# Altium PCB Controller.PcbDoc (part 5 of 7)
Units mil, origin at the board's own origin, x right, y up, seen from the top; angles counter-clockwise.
Board outline 9000 x 8000 mil, 6 copper layers (Top Layer, Layer 1, Layer 2, Layer 3, Layer 4, Bottom Layer), stack 61.699 mil thick; 761 components, 454 nets, 2369 pads, 1133 vias.
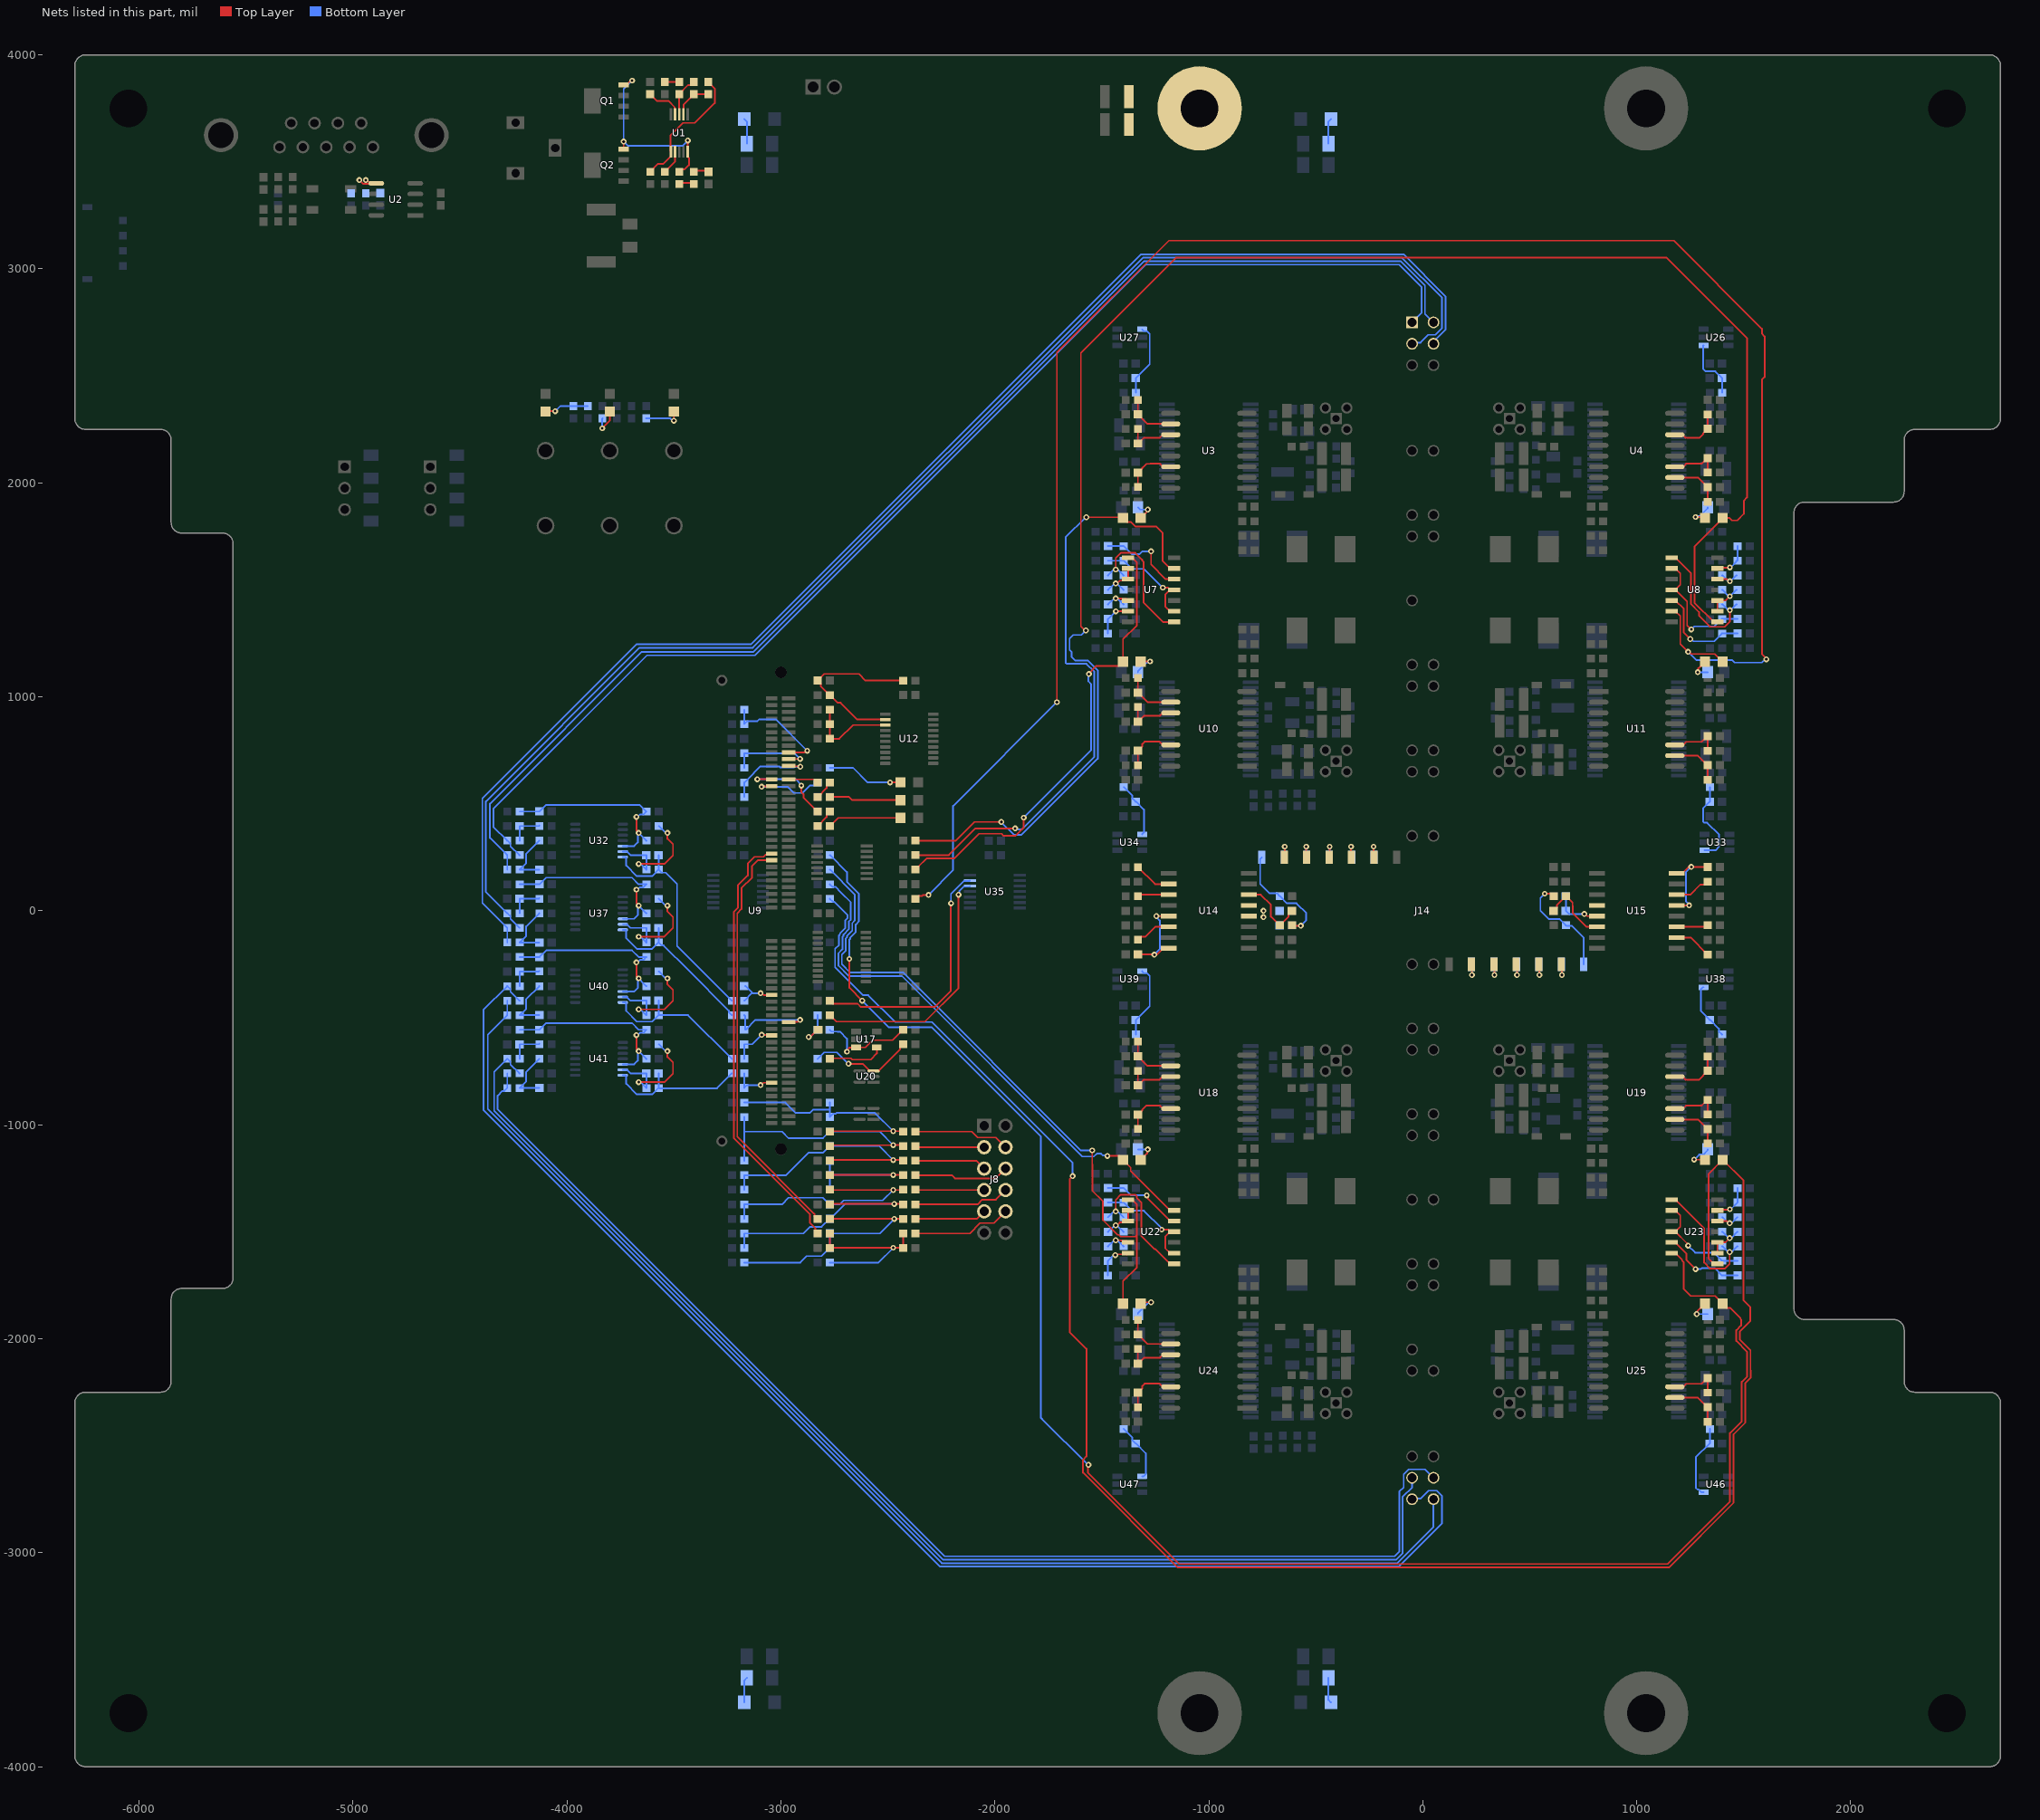
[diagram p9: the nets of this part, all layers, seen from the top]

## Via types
v1: diameter 27, hole 13, Top Layer to Bottom Layer, tented both sides, 1133 vias

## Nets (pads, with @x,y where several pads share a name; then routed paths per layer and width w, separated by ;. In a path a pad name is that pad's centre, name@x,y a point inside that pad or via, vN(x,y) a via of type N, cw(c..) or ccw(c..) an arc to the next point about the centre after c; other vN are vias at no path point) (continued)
GPIO22: R133.2 U9.72 | length 1938
  Top Layer w8: U9.72@-3042.32,236.22 -3108.78,236.22 -3135,210 -3135,155 -3184,106 -3184,8.37 -3204,-11.63 -3204,-1056 -2843.2,-1416.8 -2843.2,-1426.04 -2829.25,-1440 R133.2@-2828.62,-1440
GPIO23: R135.2 U9.74 | length 2049.9
  Top Layer w8: U9.74@-3042.32,267.72 -3048.17,261.87 -3071.48,261.87 -3081.13,252.22 -3123.56,252.22 -3155,220.78 -3155,165 -3200,120 -3200,15 -3220,-5 -3220,-1062.63 -2865,-1417.63 -2865,-1457.41 -2839.68,-1482.73 -2839.68,-1496.94 R135.2@-2828.62,-1508
HLDOO_N: C172.1 C174.1 U15.5 | length 223.3
  Top Layer w8: v1(755,-15) 758.46,-15 768.46,-25 U15.5@813.5,-25
  Bottom Layer w8: C172.1@668.58,68 C174.1@668.58,0 683.44,-14.86 715.24,-14.86 715.38,-15 v1(755,-15)
HLDOO_P: C175.1 C177.1 U14.5
  other v1: -745,-30 -745,0
IAC+_P: J14.004 R268.1 R271.1 | length 6602.4
  Bottom Layer w8: R271.1@-4278.62,-148 R268.1@-4278.62,-80 -4279.53,-80 -4395,35.47 -4395,525 -3675,1245 -3140,1245 -1317,3068 -90.12,3068 106,2871.88 106,2716 50,2660 J14.004@50,2650
IAC+_S: J14.110 R305.1 R310.1 | length 5815.8
  Bottom Layer w8: R305.1@-4278.62,-760 R310.1@-4278.62,-828 -4292.58,-841.96 -4301.96,-841.96 -4324,-864 -4324,-928.12 -2235.12,-3017 -132,-3017 -110,-2995 -110,-2715 -89.36,-2694.36 -89.36,-2633.7 -66.3,-2610.64 10.64,-2610.64 J14.110@50,-2650
IAC-_P: J14.003 R266.1 R268.2 | length 6569.5
  Bottom Layer w8: R268.2@-4221.38,-80 -4222.28,-80 -4263.76,-38.52 -4263.76,-25.96 -4277.72,-12 R266.1@-4278.62,-12 -4279.53,-12 -4379,87.47 -4379,511 -3661,1229 -3131.25,1229 -1308.25,3052 -96.75,3052 90,2865.25 90,2722.63 59.08,2691.71 25.86,2691.71 -10.64,2655.21 -44.79,2655.21 J14.003@-50,2650
IAC-_S: J14.109 R302.1 R305.2 | length 5859.4
  Bottom Layer w8: R305.2@-4221.38,-760 -4222.28,-760 -4263.76,-718.52 -4263.76,-705.96 -4277.72,-692 R302.1@-4278.62,-692 -4279.53,-692 -4340,-752.47 -4340,-934.75 -2241.75,-3033 -125.37,-3033 -94,-3001.63 -94,-2738.33 -50,-2694.33 J14.109@-50,-2650
IAC_P: C199.1 R285.2 U9.31 | length 403.7
  Top Layer w8: U9.31@-2963.58,-519.69 -2923.46,-519.69 -2913.78,-510 v1(-2910,-510)
  Bottom Layer w8: R285.2@-3171.38,-488 -3167.45,-491.93 -3167.45,-556 -3164.57,-556 -3118.57,-510 v1(-2910,-510)
IAC_S: C214.1 R304.2 U9.14 | length 207.3
  Top Layer w8: v1(-3095,-815) -3092.24,-815 -3080.9,-803.66 -3042.83,-803.66 U9.14@-3042.32,-803.15
  Bottom Layer w8: C214.1@-3171.42,-828 C214.1@-3171.42,-828 ; R304.2@-3171.38,-760 C214.1@-3171.42,-828 ; v1(-3095,-815) -3158.42,-815 C214.1@-3171.42,-828
ID0: R234.1 R241.2 U9.99 | length 420.8
  Top Layer w8: U9.99@-2963.58,677.17 -2961.68,675.26 -2911.4,675.26 v1(-2909.49,673.35)
  Bottom Layer w8: R241.2@-3171.38,532 R234.1@-3171.38,600 -3170.47,600 -3126.29,644.18 -3126.29,644.77 -3096.06,675 -3007.96,675 -3002.5,669.55 -2938.99,669.55 -2935.19,673.35 v1(-2909.49,673.35)
ID1: R227.2 R230.1 U9.101 | length 393.2
  Top Layer w8: U9.101@-2963.58,708.66 -2963.18,709.07 -2910.93,709.07 v1(-2910.53,709.47)
  Bottom Layer w8: R230.1@-3171.38,668 R227.2@-3171.38,736 -2937.06,736 v1(-2910.53,709.47)
ID2: R218.1 R222.2 U9.103 | length 525.5
  Top Layer w8: U9.103@-2963.5,740.08 U9.103@-2963.58,740.16 -2889.98,740.16 -2880,750.14 v1@-2880,755
  Bottom Layer w8: R218.1@-3171.38,940 R222.2@-3171.38,872 -3157.42,885.96 -3110.11,885.96 -3101.06,895 -3023.94,895 v1(-2876.97,748.03)
IDC+_P: J14.002 R250.1 R256.1 | length 5998.8
  Bottom Layer w8: R256.1@-4278.62,192 R250.1@-4278.62,260 -4279.53,260 -4360,340.47 -4360,500 -3650,1210 -3127.63,1210 -1301.63,3036 -181,3036 -103.37,3036 10,2922.63 10,2845 10,2790 J14.002@50,2750
IDC+_S: J14.112 R283.1 R287.1 | length 6044.7
  Bottom Layer w8: R283.1@-4278.62,-420 R287.1@-4278.62,-488 -4279.53,-488 -4370,-578.47 -4370,-927.37 -2248.37,-3049 -118.75,-3049 50,-2880.26 J14.112@50,-2750
IDC-_P: J14.001 R248.1 R250.2 | length 5887.4
  Bottom Layer w8: R250.2@-4221.38,260 -4222.28,260 -4263.76,301.48 -4263.76,314.04 -4277.72,328 R248.1@-4278.62,328 -4279.53,328 -4344,392.47 -4344,476 -3626,1194 -3121,1194 -1295,3020 -110,3020 -6,2916 -6,2794 J14.001@-50,2750
IDC-_S: J14.111 R281.1 R283.2 | length 6460.2
  Bottom Layer w8: R283.2@-4221.38,-420 -4222.28,-420 -4263.76,-378.52 -4263.76,-365.96 -4277.72,-352 R281.1@-4278.62,-352 -4279.53,-352 -4390,-462.47 -4390,-930 -2255,-3065 -112.12,-3065 89.36,-2863.52 89.36,-2733.7 65.67,-2710 27.14,-2710 -10.64,-2747.77 -47.77,-2747.77 J14.111@-50,-2750
IDC_P: C190.1 R282.2 U9.40 | length 196.7
  Top Layer w8: v1(-3095,-385) -3089.86,-385 -3081.16,-393.7 U9.40@-3042.32,-393.7
  Bottom Layer w8: R282.2@-3171.38,-420 -3170.47,-420 -3135.47,-385 -3131.57,-385 ; C190.1@-3167.45,-352 -3164.57,-352 -3131.57,-385 ; v1(-3095,-385) -3131.57,-385
IDC_S: C202.1 R299.2 U9.28 | length 220
  Top Layer w8: v1(-3089.7,-579.7) -3088.22,-581.19 -3043.81,-581.19 U9.28@-3042.32,-582.68
  Bottom Layer w8: R299.2@-3171.38,-692 C202.1@-3171.42,-624 C202.1@-3171.42,-624 -3134,-624 v1(-3089.7,-579.7) v1@-3087.35,-577.35
INP_P: C46.1 R76.2 U14.6 | length 329.1
  Top Layer w8: U14.6@-813.5,75 -757.63,75 -710,27.37 -710,-27.53 -669.53,-68 R76.2@-668.62,-68 -667.72,-68 -627.24,-27.52 -627.24,-14.86 -612.37,0 C46.1@-611.42,0
INP_S: C47.1 R72.2 U15.6 | length 324.7
  Top Layer w8: C47.1@611.42,0 612.37,0 627.24,14.86 627.24,27.52 667.72,68 R72.2@668.62,68 669.53,68 700,37.53 700,24.22 700.39,23.83 700.39,-10.39 765,-75 U15.6@813.5,-75
LED_G: R60.2 U9.96 | length 441.9
  Top Layer w8: v1(-3110.33,614.67) -3110.09,614.42 -3042.57,614.42 U9.96@-3042.32,614.17 ; v1(-2904.6,585) -2904.6,554.6 -2894.48,544.48 -2894.48,528.96 -2829.53,464 R60.2@-2828.62,464
  Bottom Layer w8: v1(-3110.33,614.67) -2929.67,614.67 -2904.6,589.6 v1(-2904.6,585)
LED_R: R233.2 U9.94 | length 343.6
  Top Layer w8: v1(-3090.33,579.67) -3088.83,581.17 -3043.83,581.17 U9.94@-3042.32,582.68
  Bottom Layer w8: v1(-3090.33,579.67) -2968.8,579.67 -2939.57,550.43 -2898.5,550.43 -2862.89,586.04 -2842.58,586.04 R233.2@-2828.62,600
LED_Y: R58.2 U9.95 | length 139.9
  Top Layer w8: U9.95@-2963.58,614.17 -2843.7,614.17 R58.2@-2829.53,600
NCP_NOTUSED: U14.4
NCS_NOTUSED: U15.4
NetC1_1: C1.1 U1.4 | length 174.2
  Top Layer w8: C1.1@-3611,3816.42 -3611,3815.47 -3580.53,3785 -3526.36,3785 -3496.47,3755.11 -3496.47,3723.87 U1.4@-3494.68,3722.09
NetC2_1: C2.1 R10.1 | length 70
  Top Layer w8: R10.1@-3400,3458.62 -3330.04,3458.62 C2.1@-3330,3458.58
NetC10_1: C10.1 R16.2 U3.10 | length 240.3
  Top Layer w8: R16.2@-1331.38,2388 C10.1@-1331.42,2320 C10.1@-1331.42,2320 -1330.47,2320 -1285.97,2275.5 -1178.28,2275.5 U3.10@-1177.78,2275
NetC13_1: C13.1 R17.2 U4.14 | length 227.8
  Top Layer w8: U4.14@1196.73,2225 1214.82,2225 1229.82,2210 1276.21,2210 1276.59,2210.38 1291.44,2210.38 1310.5,2229.44 1310.5,2232.03 1330.47,2252 C13.1@1331.42,2252 C13.1@1331.42,2252 R17.2@1331.38,2320
NetC14_1: C14.1 R18.2 U3.11 | length 238.6
  Top Layer w8: R18.2@-1331.38,2252 C14.1@-1331.42,2184 C14.1@-1331.42,2184 -1330.47,2184 -1303.97,2210.5 -1230.18,2210.5 -1215.68,2225 U3.11@-1177.78,2225
NetC15_1: C15.1 R23.2 U4.11 | length 238.6
  Top Layer w8: U4.11@1177.78,2075 1215.68,2075 1230.18,2089.5 1303.97,2089.5 1330.47,2116 C15.1@1331.42,2116 C15.1@1331.42,2116 R23.2@1331.38,2048
NetC16_1: C16.1 R26.2 U3.14 | length 227.8
  Top Layer w8: R26.2@-1331.38,1980 C16.1@-1331.42,2048 C16.1@-1331.42,2048 -1330.47,2048 -1310.5,2067.97 -1310.5,2070.56 -1292.09,2088.97 -1273.91,2088.97 -1272.88,2090 -1229.82,2090 -1214.82,2075 U3.14@-1196.73,2075
NetC17_1: C17.1 R27.2 U4.10 | length 240.3
  Top Layer w8: U4.10@1177.78,2025 1178.28,2024.5 1285.97,2024.5 1330.47,1980 C17.1@1331.42,1980 C17.1@1331.42,1980 R27.2@1331.38,1912
NetC24_1: C24.1 R41.1 R45.2 U12.2 | length 823.9
  Top Layer w8: C24.1@-2828.58,1076 C24.1@-2827.63,1076 ; U12.2@-2512.2,893.57 -2642.5,893.57 -2721.24,972.3 -2734.78,972.3 -2770.47,1008 R45.2@-2771.38,1008 -2772.28,1008 -2812.76,1048.48 -2812.76,1061.14 C24.1@-2827.63,1076 ; R41.1@-2428.62,1076 -2604.41,1076 -2635.28,1106.86 -2796.76,1106.86 C24.1@-2827.63,1076
NetC25_1: C25.1 R40.2 U10.10 | length 240.3
  Top Layer w8: R40.2@-1331.38,1088 C25.1@-1331.42,1020 C25.1@-1331.42,1020 -1330.47,1020 -1285.97,975.5 -1178.28,975.5 U10.10@-1177.78,975
NetC28_1: C28.1 R46.2 U10.11 | length 238.6
  Top Layer w8: R46.2@-1331.38,952 C28.1@-1331.42,884 C28.1@-1331.42,884 -1330.47,884 -1303.97,910.5 -1230.18,910.5 -1215.68,925 U10.11@-1177.78,925
NetC29_1: C29.1 R47.1 R52.2 U12.3 | length 421.7
  Top Layer w8: R47.1@-2771.38,940 R47.1@-2771.38,940 C29.1@-2771.42,872 C29.1@-2771.42,872 R52.2@-2771.38,804 -2727.22,804 -2663.25,867.98 U12.3@-2512.2,867.98
NetC30_1: C30.1 R53.2 U11.11 | length 238.6
  Top Layer w8: U11.11@1177.78,775 1215.68,775 1230.18,789.5 1303.97,789.5 1330.47,816 C30.1@1331.42,816 C30.1@1331.42,816 R53.2@1331.38,748
NetC31_1: C31.1 R55.2 U10.14 | length 232.1
  Top Layer w8: R55.2@-1331.38,680 C31.1@-1331.42,748 C31.1@-1331.42,748 ; C31.1@-1330.47,748 -1310.5,767.97 -1310.5,779.5 -1300,790 -1229.82,790 -1214.82,775 U10.14@-1196.73,775
NetC34_1: C34.1 R57.2 U11.10 | length 240.3
  Top Layer w8: U11.10@1177.78,725 1178.28,724.5 1285.97,724.5 1330.47,680 C34.1@1331.42,680 C34.1@1331.42,680 R57.2@1331.38,612
NetC39_1: C39.1 U15.13 U15.16 | length 412.4
  Top Layer w8: U15.13@1186.5,25 v1(1245,25) ; U15.16@1186.5,175 1212.5,175 1241.5,204 C39.1@1331.42,204
  Bottom Layer w8: v1(1245,25) 1245,30.06 1229.5,45.56 1229.5,179.5 v1(1255,205)
NetC52_1: C52.1 U14.13 U14.16 | length 412.4
  Top Layer w8: C52.1@-1331.42,-204 -1241.5,-204 -1212.5,-175 U14.16@-1186.5,-175 ; v1(-1245,-25) U14.13@-1186.5,-25
  Bottom Layer w8: v1(-1255,-205) -1229.5,-179.5 -1229.5,-45.56 -1245,-30.06 v1(-1245,-25)
NetC54_1: C54.1 R288.2 U17.3 | length 467.7
  Top Layer w8: v1(-2691.44,-658.56) -2687.8,-654.93 -2687.8,-647.8 -2680.17,-640.17 -2650,-640.17 U17.3@-2648.23,-638.4 -2605.16,-638.4 -2571.39,-604.63 -2478.16,-604.63 -2429.53,-556 C54.1@-2428.58,-556
  Bottom Layer w8: R288.2@-2771.38,-556 -2762.88,-564.5 -2735.5,-564.5 -2735.19,-564.81 -2724.12,-564.81 -2691.44,-597.5 v1(-2691.44,-658.56)
NetC59_1: C59.1 R94.2 U18.10 | length 240.3
  Top Layer w8: R94.2@-1331.38,-612 C59.1@-1331.42,-680 C59.1@-1331.42,-680 -1330.47,-680 -1285.97,-724.5 -1178.28,-724.5 U18.10@-1177.78,-725
NetC62_1: C62.1 R96.2 U19.14 | length 227.8
  Top Layer w8: U19.14@1196.73,-775 1214.82,-775 1229.82,-790 1276.21,-790 1276.59,-789.62 1291.44,-789.62 1310.5,-770.56 1310.5,-767.97 1330.47,-748 C62.1@1331.42,-748 C62.1@1331.42,-748 R96.2@1331.38,-680
NetC63_1: C63.1 R99.2 U18.11 | length 238.6
  Top Layer w8: R99.2@-1331.38,-748 C63.1@-1331.42,-816 C63.1@-1331.42,-816 -1330.47,-816 -1303.97,-789.5 -1230.18,-789.5 -1215.68,-775 U18.11@-1177.78,-775
NetC65_1: C65.1 R109.2 U19.11 | length 238.6
  Top Layer w8: U19.11@1177.78,-925 1215.68,-925 1230.18,-910.5 1303.97,-910.5 1330.47,-884 C65.1@1331.42,-884 C65.1@1331.42,-884 R109.2@1331.38,-952
NetC66_1: C66.1 R113.2 U18.14 | length 227.8
  Top Layer w8: R113.2@-1331.38,-1020 C66.1@-1331.42,-952 C66.1@-1331.42,-952 -1330.47,-952 -1310.5,-932.03 -1310.5,-929.44 -1291.44,-910.38 -1276.59,-910.38 -1276.21,-910 -1229.82,-910 -1214.82,-925 U18.14@-1196.73,-925
NetC68_1: C68.1 R116.2 U19.10 | length 240.3
  Top Layer w8: U19.10@1177.78,-975 1178.28,-975.5 1285.97,-975.5 1330.47,-1020 C68.1@1331.42,-1020 C68.1@1331.42,-1020 R116.2@1331.38,-1088
NetC72_1: C72.1 R135.1 R136.2 R137.1 R351.2 | length 804.6
  Top Layer w8: R135.1@-2771.38,-1508 R137.1@-2771.38,-1576 -2770.38,-1575 v1(-2475,-1575) -2429.58,-1575 C72.1@-2428.58,-1576 R136.2@-2428.62,-1508 R136.2@-2428.62,-1508
  Bottom Layer w8: R351.2@-2771.38,-1644 -2544,-1644 v1(-2475,-1575)
NetC76_1: C76.1 R144.2 U24.10 | length 240.3
  Top Layer w8: R144.2@-1331.38,-1912 C76.1@-1331.42,-1980 C76.1@-1331.42,-1980 -1330.47,-1980 -1285.97,-2024.5 -1178.28,-2024.5 U24.10@-1177.78,-2025
NetC78_1: C78.1 R148.2 U24.11 | length 238.6
  Top Layer w8: R148.2@-1331.38,-2048 C78.1@-1331.42,-2116 C78.1@-1331.42,-2116 -1330.47,-2116 -1303.97,-2089.5 -1230.18,-2089.5 -1215.68,-2075 U24.11@-1177.78,-2075
NetC79_1: C79.1 R153.2 U25.11 | length 238.6
  Top Layer w8: U25.11@1177.78,-2225 1215.68,-2225 1230.18,-2210.5 1303.97,-2210.5 1330.47,-2184 C79.1@1331.42,-2184 C79.1@1331.42,-2184 R153.2@1331.38,-2252
NetC80_1: C80.1 R154.2 U24.14 | length 232.1
  Top Layer w8: R154.2@-1331.38,-2320 C80.1@-1331.42,-2252 C80.1@-1331.42,-2252 ; C80.1@-1330.47,-2252 -1310.5,-2232.03 -1310.5,-2220.5 -1300,-2210 -1229.82,-2210 -1214.82,-2225 U24.14@-1196.73,-2225
NetC83_1: C83.1 R155.2 U25.10 | length 240.3
  Top Layer w8: U25.10@1177.78,-2275 1178.28,-2275.5 1285.97,-2275.5 1330.47,-2320 C83.1@1331.42,-2320 C83.1@1331.42,-2320 R155.2@1331.38,-2388
NetC87_1: C87.1 R160.1 R161.1 U2.5 | length 111.6
  Top Layer w8: v1(-4970,3415) -4952.45,3397.45 U2.5@-4920.82,3397.45 ; v1(-4940,3415) -4935.82,3415 -4920.82,3400 U2.5@-4891.09,3400
NetC91_1: C91.1 R162.1 U26.1 | length 284.7
  Bottom Layer w8: U26.1@1311.93,2642.6 1309.61,2640.28 1309.61,2534.17 1322.91,2520.86 1366.76,2520.86 1397.63,2490 C91.1@1398.58,2490 C91.1@1398.58,2490 R162.1@1398.62,2422
NetC92_1: C92.1 R163.1 U27.1 | length 346.4
  Bottom Layer w8: R163.1@-1341.38,2422 C92.1@-1341.42,2490 C92.1@-1341.42,2490 -1340.47,2490 -1276.31,2554.17 -1276.31,2696.64 -1288.27,2708.61 -1303.13,2708.61 U27.1@-1311.93,2717.4
NetC116_1: C116.1 R192.1 U7.5 | length 420.1
  Top Layer w8: v1(-1270,1680) -1270,1618.46 -1201.54,1550 U7.5@-1162.75,1550
  Bottom Layer w8: C116.1@-1471.42,1704 R192.1@-1398.62,1704 -1397.72,1704 -1359.67,1665.96 -1324.43,1665.96 -1310.38,1680 v1(-1270,1680)
NetC117_1: C117.1 R191.1 U8.13 | length 174.1
  Top Layer w8: U8.13@1377.25,1600 1379.75,1602.5 1432.5,1602.5 v1(1435,1605)
  Bottom Layer w8: v1(1435,1605) 1439.47,1605 1465.47,1631 C117.1@1465.47,1636 ; C117.1@1471.42,1636 R191.1@1471.38,1704 R191.1@1471.38,1704
NetC118_1: C118.1 R194.1 U7.2 U7.4 | length 501.8
  Top Layer w8: v1(-1215,1510) -1190.5,1510 U7.4@-1180.5,1500 ; U7.2@-1162.75,1400 -1180.5,1400 -1203.5,1423 -1203.5,1477 U7.4@-1180.5,1500 ; U7.4@-1162.75,1500 U7.4@-1180.5,1500
  Bottom Layer w8: C118.1@-1471.42,1636 R194.1@-1398.62,1636 -1397.72,1636 -1359.67,1597.96 -1302.96,1597.96 v1(-1215,1510)
NetC119_1: C119.1 R195.1 U8.12 | length 152.9
  Top Layer w8: U8.12@1377.25,1550 1419.86,1550 1429.86,1540 v1(1435,1540)
  Bottom Layer w8: R195.1@1398.62,1568 1399.53,1568 1423.89,1543.64 1431.36,1543.64 v1(1435,1540) 1437.47,1540 1465.47,1568 C119.1@1466.38,1568
NetC120_1: C120.1 R196.1 U7.1 | length 679.1
  Top Layer w8: v1(-1435,1595) -1435,1648.97 -1410.97,1673 -1343.53,1673 -1311.4,1640.87 -1311.4,1637.23 -1305.5,1631.34 -1305.5,1440.5 -1215,1350 U7.1@-1162.75,1350
  Bottom Layer w8: C120.1@-1471.42,1568 -1470.47,1568 -1447.11,1591.36 -1438.64,1591.36 v1(-1435,1595) -1431.36,1591.36 -1422.89,1591.36 -1399.53,1568 R196.1@-1398.62,1568
NetC121_1: C121.1 R197.1 U8.9 U8.10 | length 208.7
  Top Layer w8: U8.9@1377.25,1400 U8.10@1377.25,1450 1415,1450 v1(1435,1470)
  Bottom Layer w8: R197.1@1398.62,1500 1399.53,1500 1425.89,1473.64 1431.36,1473.64 v1(1435,1470) 1435.47,1470 1465.47,1500 C121.1@1466.38,1500
NetC122_1: C122.1 R198.1 U7.9 U7.10 | length 213.7
  Top Layer w8: v1(-1435,1530) -1429.86,1530 -1416.86,1543 -1384.25,1543 U7.10@-1377.25,1550 U7.9@-1377.25,1600
  Bottom Layer w8: C122.1@-1471.42,1500 -1470.47,1500 -1444.11,1526.36 -1438.64,1526.36 v1(-1435,1530) -1431.36,1526.36 -1425.89,1526.36 -1399.53,1500 R198.1@-1398.62,1500
NetC123_1: C123.1 R199.1 U8.1 | length 653.8
  Top Layer w8: U8.1@1162.75,1650 1180.5,1650 1254,1576.5 1254,1432.87 1291,1395.87 1291,1379.53 1343.53,1327 1410.97,1327 1435,1351.03 v1(1435,1405)
  Bottom Layer w8: R199.1@1398.62,1432 1399.53,1432 1422.89,1408.64 1431.36,1408.64 v1(1435,1405) 1438.47,1405 1465.47,1432 C123.1@1466.38,1432
NetC124_1: C124.1 R200.1 U7.12 | length 157.9
  Top Layer w8: v1(-1435,1460) -1409.5,1460 -1406.5,1457 -1384.25,1457 U7.12@-1377.25,1450
  Bottom Layer w8: C124.1@-1471.42,1432 -1470.47,1432 -1446.11,1456.36 -1438.64,1456.36 v1(-1435,1460) -1431.36,1456.36 -1423.89,1456.36 -1399.53,1432 R200.1@-1398.62,1432
NetC125_1: C125.1 R201.1 U8.2 U8.4 | length 606.5
  Top Layer w8: U8.4@1162.75,1500 U8.4@1180.5,1500 ; U8.2@1162.75,1600 1180.5,1600 1203.5,1577 1203.5,1523 U8.4@1180.5,1500 ; v1(1254.5,1315) 1235.5,1334 1235.5,1445 U8.4@1180.5,1500
  Bottom Layer w8: v1(1254.5,1315) 1268.78,1329.28 1363,1329.28 R201.1@1397.72,1364 ; R201.1@1398.62,1364 C125.1@1471.42,1364
NetC126_1: C126.1 R204.1 U7.13 | length 176.2
  Top Layer w8: v1(-1434.75,1399.8) -1434.65,1399.9 -1377.35,1399.9 U7.13@-1377.25,1400
  Bottom Layer w8: R204.1@-1471.38,1296 C126.1@-1471.42,1364 C126.1@-1471.42,1364 ; C126.1@-1470.47,1364 -1434.75,1399.73 v1(-1434.75,1399.8)
NetC127_1: C127.1 R203.1 U8.5 | length 467.4
  Top Layer w8: U8.5@1162.75,1450 1180.5,1450 1219.5,1411 1219.5,1300.5 v1(1250,1270)
  Bottom Layer w8: v1(1250,1270) 1255.14,1270 1265.64,1259.5 1361.22,1259.5 1397.72,1296 R203.1@1398.62,1296 C127.1@1471.42,1296
NetC152_1: C152.1 R235.1 U33.1 | length 406.3
  Bottom Layer w8: U33.1@1316.93,282.6 1367.6,282.6 1385,300 1385,355 1328.86,411.14 1316.64,411.14 1309.61,418.17 1309.61,479.14 1340.47,510 C152.1@1341.42,510 R235.1@1341.38,578 R235.1@1341.38,578 R235.1@1342.28,578
NetC153_1: C153.1 R236.1 U34.1 | length 265.3
  Bottom Layer w8: R236.1@-1398.62,578 -1397.72,578 -1357.24,537.52 -1357.24,524.86 -1342.37,510 C153.1@-1341.42,510 -1340.47,510 -1303.32,472.85 -1303.32,366.01 U34.1@-1311.93,357.4
NetC156_1: C156.1 R242.1 R243.2 R246.2 U32.12 | length 929.4
  Top Layer w8: v1(-3675,439) -3675,374 v1(-3665,364)
  Bottom Layer w8: R243.2@-4221.38,464 C156.1@-4128.58,464 -4127.63,464 -4096.76,494.86 -3660.39,494.86 -3629.53,464 R242.1@-3628.62,464 -3642.58,450.04 -3658.81,450.04 -3669.86,439 v1(-3675,439) ; U32.12@-3738.78,302.41 -3685.53,302.41 -3668.44,319.5 -3668.44,360.56 v1(-3665,364) -3664.62,364 -3652.44,351.81 -3652.44,350.91 -3629.53,328 R246.2@-3628.62,328
NetC161_1: C161.1 R245.1 R248.2 | length 162.1
  Bottom Layer w8: R248.2@-4221.38,328 C161.1@-4221.42,396 C161.1@-4221.42,396 -4131.62,396 R245.1@-4128.62,399
NetC167_1: C167.1 R244.2 R255.2 U32.13 | length 566.1
  Top Layer w8: v1(-3665,219) -3545,219 -3504.5,259.5 -3504.5,310.9 -3530,336.4 v1(-3530,364)
  Bottom Layer w8: U32.13@-3738.78,276.82 -3719.94,276.82 -3703.12,260 C167.1@-3628.58,260 C167.1@-3628.58,260 R255.2@-3628.62,192 -3629.53,192 v1@-3652.89,215.36 ; R244.2@-3571.38,396 -3570.47,396 -3542.11,367.64 -3533.64,367.64 v1(-3530,364)
NetC167_2: C167.2 R255.1 R282.1 U32.14 | length 1072.2
  Bottom Layer w8: U32.14@-3738.78,251.23 -3725.42,251.23 -3722.75,248.56 -3722.75,211.75 -3673.04,162.04 -3602.24,162.04 -3572.28,192 R255.1@-3571.38,192 ; C167.2@-3571.42,260 R255.1@-3571.38,192 R255.1@-3571.38,192 ; R282.1@-3228.62,-420 -3229.53,-420 -3485.43,-164.1 -3485.43,125.43 -3538.04,178.04 -3557.42,178.04 R255.1@-3571.38,192
NetC169_1: C169.1 R247.1 R256.2 | length 287.1
  Bottom Layer w8: R256.2@-4207.42,205.96 R256.2@-4221.38,192 R256.2@-4220.47,192 ; C169.1@-4128.58,192 R256.2@-4220.47,192 ; R247.1@-4128.62,328 -4129.53,328 -4190.5,267.03 -4190.5,221.97 R256.2@-4220.47,192
NetC171_1: C171.1 R258.1 R259.2 R264.2 U37.12 | length 929.4
  Top Layer w8: v1(-3675,99) -3675,34 v1(-3665,24)
  Bottom Layer w8: R259.2@-4221.38,124 C171.1@-4128.58,124 -4127.63,124 -4096.76,154.86 -3695.86,154.86 -3665,124 R258.1@-3628.62,124 -3642.58,110.04 -3658.81,110.04 -3669.86,99 v1(-3675,99) ; U37.12@-3738.78,-37.59 -3685.53,-37.59 -3668.44,-20.5 -3668.44,20.56 v1(-3665,24) -3664.62,24 -3652.44,11.81 -3652.44,10.91 -3629.53,-12 R264.2@-3628.62,-12
NetC173_1: C173.1 R263.1 R266.2 | length 162.1
  Bottom Layer w8: R266.2@-4221.38,-12 C173.1@-4221.42,56 C173.1@-4221.42,56 -4131.62,56 R263.1@-4128.62,59
NetC180_1: C180.1 R262.2 R270.2 U37.13 | length 566.1
  Top Layer w8: v1(-3665,-121) -3545,-121 -3504.5,-80.5 -3504.5,-29.1 -3530,-3.6 v1(-3530,24)
  Bottom Layer w8: U37.13@-3738.78,-63.18 -3719.94,-63.18 -3703.12,-80 C180.1@-3628.58,-80 C180.1@-3628.58,-80 R270.2@-3628.62,-148 -3629.53,-148 v1@-3652.89,-124.64 ; R262.2@-3571.38,56 -3570.47,56 -3542.11,27.64 -3533.64,27.64 v1(-3530,24)
NetC180_2: C180.2 R270.1 R285.1 U37.14 | length 794.3
  Bottom Layer w8: U37.14@-3738.78,-88.77 -3725.42,-88.77 -3722.75,-91.44 -3722.75,-128.25 -3673.04,-177.96 -3602.24,-177.96 R270.1@-3572.28,-148 ; R270.1@-3571.38,-148 -3557.42,-161.96 -3547.98,-161.96 -3432.53,-277.41 -3243.48,-466.45 -3243.48,-474.04 -3229.53,-488 R285.1@-3228.62,-488 ; C180.2@-3571.42,-80 R270.1@-3571.38,-148 R270.1@-3570.52,-147.96
NetC184_1: C184.1 R265.1 R271.2 | length 287.1
  Bottom Layer w8: R271.2@-4207.42,-134.04 R271.2@-4221.38,-148 R271.2@-4220.47,-148 ; C184.1@-4128.58,-148 R271.2@-4220.47,-148 ; R265.1@-4128.62,-12 -4129.53,-12 -4190.5,-72.97 -4190.5,-118.03 R271.2@-4220.47,-148
NetC186_1: C186.1 R272.1 R273.2 R279.2 U40.12 | length 929.4
  Top Layer w8: v1(-3675,-241) -3675,-306 v1(-3665,-316)
  Bottom Layer w8: R273.2@-4221.38,-216 C186.1@-4128.58,-216 -4127.63,-216 -4096.76,-185.14 -3695.86,-185.14 -3665,-216 R272.1@-3628.62,-216 -3642.58,-229.96 -3658.81,-229.96 -3669.86,-241 v1(-3675,-241) ; U40.12@-3738.78,-377.59 -3685.53,-377.59 -3668.44,-360.5 -3668.44,-319.44 v1(-3665,-316) -3664.62,-316 -3652.44,-328.19 -3652.44,-329.09 -3629.53,-352 R279.2@-3628.62,-352
NetC188_1: C188.1 R278.1 R281.2 | length 162.1
  Bottom Layer w8: R281.2@-4221.38,-352 C188.1@-4221.42,-284 C188.1@-4221.42,-284 -4131.62,-284 R278.1@-4128.62,-281
NetC192_1: C192.1 R277.2 R286.2 U40.13 | length 566.1
  Top Layer w8: v1(-3665,-461) -3545,-461 -3504.5,-420.5 -3504.5,-369.1 -3530,-343.6 v1(-3530,-316)
  Bottom Layer w8: U40.13@-3738.78,-403.18 -3719.94,-403.18 -3703.12,-420 C192.1@-3628.58,-420 C192.1@-3628.58,-420 R286.2@-3628.62,-488 -3629.53,-488 v1@-3652.89,-464.64 ; R277.2@-3571.38,-284 -3570.47,-284 -3542.11,-312.36 -3533.64,-312.36 v1(-3530,-316)
NetC192_2: C192.2 R286.1 R299.1 U40.14 | length 733.6
  Bottom Layer w8: U40.14@-3738.78,-428.77 -3725.42,-428.77 -3722.75,-431.44 -3722.75,-468.25 -3673.04,-517.96 -3602.24,-517.96 -3572.28,-488 R286.1@-3571.38,-488 ; C192.2@-3571.42,-420 R286.1@-3571.38,-488 R286.1@-3571.38,-488 ; R299.1@-3228.62,-692 -3229.53,-692 -3433.53,-488 R286.1@-3571.38,-488
NetC196_1: C196.1 R280.1 R287.2 | length 287.1
  Bottom Layer w8: R287.2@-4207.42,-474.04 R287.2@-4221.38,-488 R287.2@-4220.47,-488 ; C196.1@-4128.58,-488 R287.2@-4220.47,-488 ; R280.1@-4128.62,-352 -4129.53,-352 -4190.5,-412.97 -4190.5,-458.03 R287.2@-4220.47,-488
NetC197_1: C197.1 R291.1 U38.1 | length 269.9
  Bottom Layer w8: U38.1@1311.93,-357.4 1308.8,-357.4 1300,-366.2 1300,-469.53 1340.47,-510 1342.37,-510 1383.76,-551.39 1383.76,-564.04 1397.72,-578 R291.1@1398.62,-578
NetC198_1: C198.1 R292.1 U39.1 | length 346.4
  Bottom Layer w8: R292.1@-1341.38,-578 C198.1@-1341.42,-510 C198.1@-1341.42,-510 -1340.47,-510 -1276.31,-445.83 -1276.31,-303.36 -1288.27,-291.39 -1303.13,-291.39 U39.1@-1311.93,-282.6
NetC200_1: C200.1 R289.1 R290.2 R300.2 U41.12 | length 929.4
  Top Layer w8: v1(-3675,-581) -3675,-646 v1(-3665,-656)
  Bottom Layer w8: R290.2@-4221.38,-556 C200.1@-4128.58,-556 -4127.63,-556 -4096.76,-525.14 -3695.86,-525.14 -3665,-556 R289.1@-3628.62,-556 -3642.58,-569.96 -3658.81,-569.96 -3669.86,-581 v1(-3675,-581) ; U41.12@-3738.78,-717.59 -3685.53,-717.59 -3668.44,-700.5 -3668.44,-659.44 v1(-3665,-656) -3664.62,-656 -3652.44,-668.19 -3652.44,-669.09 -3629.53,-692 R300.2@-3628.62,-692
NetC203_1: C203.1 R294.1 R302.2 | length 162.1
  Bottom Layer w8: R302.2@-4221.38,-692 C203.1@-4221.42,-624 C203.1@-4221.42,-624 -4131.62,-624 R294.1@-4128.62,-621
NetC210_1: C210.1 R293.2 R309.2 U41.13 | length 566.1
  Top Layer w8: v1(-3665,-801) -3545,-801 -3504.5,-760.5 -3504.5,-709.1 -3530,-683.6 v1(-3530,-656)
  Bottom Layer w8: U41.13@-3738.78,-743.18 -3719.94,-743.18 -3703.12,-760 C210.1@-3628.58,-760 C210.1@-3628.58,-760 R309.2@-3628.62,-828 -3629.53,-828 v1@-3652.89,-804.64 ; R293.2@-3571.38,-624 -3570.47,-624 -3542.11,-652.36 -3533.64,-652.36 v1(-3530,-656)
NetC210_2: C210.2 R304.1 R309.1 U41.14 | length 678.5
  Bottom Layer w8: U41.14@-3738.78,-768.77 -3725.42,-768.77 -3722.75,-771.44 -3722.75,-808.25 -3673.04,-857.96 -3602.24,-857.96 R309.1@-3572.28,-828 ; C210.2@-3571.42,-760 R309.1@-3571.38,-828 R309.1@-3571.38,-828 -3569.38,-830 -3298.62,-830 -3243.48,-774.86 -3243.48,-773.96 -3229.53,-760 R304.1@-3228.62,-760
NetC215_1: C215.1 R301.1 R310.2 | length 287.1
  Bottom Layer w8: R310.2@-4207.42,-814.04 R310.2@-4221.38,-828 R310.2@-4220.47,-828 ; C215.1@-4128.58,-828 R310.2@-4220.47,-828 ; R301.1@-4128.62,-692 -4129.53,-692 -4190.5,-752.97 -4190.5,-798.03 R310.2@-4220.47,-828
NetC224_1: C224.1 R114.1 R115.2 R313.2 R314.1 | length 1178.8
  Top Layer w8: R114.1@-2771.38,-1032 -2769.38,-1030 v1(-2475,-1030) -2430.62,-1030 R115.2@-2428.62,-1032
  Bottom Layer w8: R314.1@-3171.38,-896 -2979,-896 -2930,-945 -2865.22,-945 -2850.2,-929.98 -2771.38,-929.98 ; C224.1@-2771.42,-964 C224.1@-2771.42,-964 ; R313.2@-2771.38,-896 -2771.38,-929.98 ; v1(-2475,-1030) -2560.5,-944.5 -2740.56,-944.5 -2745.2,-949.14 -2756.56,-949.14 C224.1@-2771.42,-964 ; C224.1@-2771.42,-964 -2771.38,-929.98
NetC228_1: C228.1 R117.1 R118.2 R319.1 R326.2 | length 1298.9
  Top Layer w8: R117.1@-2771.38,-1100 -2766.88,-1095.5 -2475.5,-1095.5 v1(-2475,-1095) -2433.62,-1095 R118.2@-2428.62,-1100
  Bottom Layer w8: R326.2@-3171.38,-1168 -3171.38,-1032 ; R319.1@-3171.38,-964 -3171.38,-1032 ; v1(-2475,-1095) -2538,-1032 C228.1@-2771.42,-1032 -2772.37,-1032 -2803.24,-1062.86 -2964.45,-1062.86 -2995.31,-1032 -3171.38,-1032
NetC229_1: C229.1 R119.1 R120.2 R331.2 R335.1 | length 1193.6
  Top Layer w8: R119.1@-2771.38,-1168 -2768.38,-1165 v1(-2475,-1165) -2431.62,-1165 R120.2@-2428.62,-1168
  Bottom Layer w8: R335.1@-3171.38,-1304 R331.2@-3171.38,-1236 -2976,-1236 -2870,-1130 -2854.22,-1130 -2853.36,-1130.86 -2803.24,-1130.86 -2772.37,-1100 C229.1@-2771.42,-1100 -2540,-1100 v1(-2475,-1165)
NetC230_1: C230.1 R123.1 R124.2 R330.2 R334.1 | length 776.4
  Top Layer w8: R123.1@-2771.38,-1236 -2770.38,-1235 v1(-2475,-1235) -2429.62,-1235 R124.2@-2428.62,-1236
  Bottom Layer w8: R334.1@-2771.38,-1304 R330.2@-2771.38,-1236 ; C230.1@-2771.42,-1168 R330.2@-2771.38,-1236 R330.2@-2771.38,-1236 ; v1(-2475,-1235) -2770.38,-1235 R330.2@-2771.38,-1236
NetC232_1: C232.1 R333.1 U22.5 | length 378.6
  Top Layer w8: v1(-1290,-1330) -1286.36,-1333.64 -1286.36,-1344.14 -1180.5,-1450 U22.5@-1162.75,-1450
  Bottom Layer w8: C232.1@-1471.42,-1296 R333.1@-1398.62,-1296 -1397.72,-1296 -1363.72,-1330 v1(-1290,-1330)
NetC233_1: C233.1 R332.1 U23.13 | length 176.5
  Top Layer w8: U23.13@1377.25,-1400 1379.75,-1397.5 1432.5,-1397.5 v1(1435,-1395)
  Bottom Layer w8: v1(1435,-1395) 1439.47,-1395 1471.38,-1363.09 R332.1@1471.38,-1296
NetC234_1: C234.1 R337.1 U22.2 U22.4 | length 504.7
  Top Layer w8: v1(-1220,-1490) -1190.5,-1490 U22.4@-1180.5,-1500 ; U22.2@-1162.75,-1600 -1180.5,-1600 -1203.5,-1577 -1203.5,-1523 U22.4@-1180.5,-1500 ; U22.4@-1162.75,-1500 U22.4@-1180.5,-1500
  Bottom Layer w8: C234.1@-1471.42,-1364 R337.1@-1398.62,-1364 -1397.72,-1364 -1359.67,-1402.04 -1302.96,-1402.04 -1220,-1485 v1(-1220,-1490)
NetC235_1: C235.1 R127.1 R128.2 R338.1 R341.2 | length 1161.3
  Top Layer w8: R127.1@-2771.38,-1304 -2770.38,-1305 v1(-2475,-1305) -2429.62,-1305 R128.2@-2428.62,-1304
  Bottom Layer w8: R341.2@-3171.38,-1440 R338.1@-3171.38,-1372 -2995.31,-1372 -2964.45,-1341.14 -2803.24,-1341.14 -2772.37,-1372 C235.1@-2771.42,-1372 -2725.1,-1372 -2707.1,-1354 -2524,-1354 v1(-2475,-1305)
NetC236_1: C236.1 R339.1 U23.12 | length 156.9
  Top Layer w8: U23.12@1377.25,-1450 1418.91,-1450 1428.91,-1460 v1(1434.05,-1460)
  Bottom Layer w8: R339.1@1398.62,-1432 1399.53,-1432 1423.89,-1456.36 1430.41,-1456.36 v1(1434.05,-1460) 1437.68,-1456.36 1446.11,-1456.36 1470.47,-1432 C236.1@1471.42,-1432
NetC237_1: C237.1 R340.1 U22.1 | length 661.5
  Top Layer w8: v1(-1435,-1405) -1435,-1351.03 -1410.97,-1327 -1343.53,-1327 -1336.5,-1334.03 -1336.5,-1342.19 -1315.5,-1363.19 -1315.5,-1519.5 -1253.5,-1581.5 -1249,-1581.5 -1180.5,-1650 U22.1@-1162.75,-1650
  Bottom Layer w8: C237.1@-1471.42,-1432 -1470.47,-1432 -1447.11,-1408.64 -1438.64,-1408.64 v1(-1435,-1405) -1431.36,-1408.64 -1422.89,-1408.64 -1399.53,-1432 R340.1@-1398.62,-1432
NetC238_1: C238.1 R131.1 R132.2 R344.2 R348.1 | length 1171
  Top Layer w8: R131.1@-2771.38,-1372 -2769.38,-1370 v1(-2470,-1370) -2430.62,-1370 R132.2@-2428.62,-1372
  Bottom Layer w8: R348.1@-3171.38,-1576 R344.2@-3171.38,-1508 -2894.06,-1508 -2863.2,-1477.14 -2809.51,-1477.14 -2772.37,-1440 C238.1@-2771.42,-1440 -2770.47,-1440 -2700.47,-1370 v1(-2470,-1370)
NetC239_1: C239.1 R342.1 U23.9 U23.10 | length 212.7
  Top Layer w8: U23.9@1377.25,-1600 U23.10@1377.25,-1550 1414.05,-1550 v1(1434.05,-1530)
  Bottom Layer w8: R342.1@1398.62,-1500 1399.53,-1500 1429.53,-1530 v1(1434.05,-1530) 1437.68,-1526.36 1444.11,-1526.36 1470.47,-1500 C239.1@1471.42,-1500
NetC240_1: C240.1 R343.1 U22.9 U22.10 | length 213.7
  Top Layer w8: v1(-1435,-1470) -1429.86,-1470 -1416.86,-1457 -1384.25,-1457 U22.10@-1377.25,-1450 U22.9@-1377.25,-1400
  Bottom Layer w8: C240.1@-1471.42,-1500 -1470.47,-1500 -1444.11,-1473.64 -1438.64,-1473.64 v1(-1435,-1470) -1431.36,-1473.64 -1425.89,-1473.64 -1399.53,-1500 R343.1@-1398.62,-1500
NetC241_1: C241.1 R133.1 R134.2 R347.2 R352.1 | length 1168.5
  Top Layer w8: R133.1@-2771.38,-1440 v1(-2470,-1440) R134.2@-2428.62,-1440
  Bottom Layer w8: R352.1@-3171.38,-1644 -2909.56,-1644 -2879.61,-1614.04 -2810.33,-1614.04 -2772.28,-1576 R347.2@-2771.38,-1576 C241.1@-2771.42,-1508 C241.1@-2771.42,-1508 -2538,-1508 v1(-2470,-1440)
NetC242_1: C242.1 R345.1 U23.1 | length 658.4
  Top Layer w8: U23.1@1162.75,-1350 1180.5,-1350 1315,-1484.5 1315,-1644.47 1343.53,-1673 1410.97,-1673 1434.05,-1649.92 v1(1434.05,-1595)
  Bottom Layer w8: R345.1@1398.62,-1568 1399.53,-1568 1422.89,-1591.36 1430.41,-1591.36 v1(1434.05,-1595) 1437.68,-1591.36 1447.11,-1591.36 1470.47,-1568 C242.1@1471.42,-1568
NetC243_1: C243.1 R346.1 U22.12 | length 157.9
  Top Layer w8: v1(-1435,-1540) -1409.5,-1540 -1406.5,-1543 -1384.25,-1543 U22.12@-1377.25,-1550
  Bottom Layer w8: C243.1@-1471.42,-1568 -1470.47,-1568 -1446.11,-1543.64 -1438.64,-1543.64 v1(-1435,-1540) -1431.36,-1543.64 -1423.89,-1543.64 -1399.53,-1568 R346.1@-1398.62,-1568
NetC244_1: C244.1 R349.1 U23.2 U23.4 | length 505
  Top Layer w8: U23.4@1162.75,-1500 U23.4@1180.5,-1500 ; U23.2@1162.75,-1400 1180.5,-1400 1203.5,-1423 1203.5,-1477 U23.4@1180.5,-1500 ; v1(1240,-1565) 1236.36,-1561.36 1236.36,-1555.86 U23.4@1180.5,-1500
  Bottom Layer w8: v1(1240,-1565) 1272.96,-1597.96 1359.67,-1597.96 1397.72,-1636 C244.1@1471.42,-1636
NetC245_1: C245.1 R354.1 U22.13 | length 178.4
  Top Layer w8: v1(-1437.02,-1609.07) -1433.39,-1605.44 -1385.81,-1605.44 -1384.25,-1607 U22.13@-1377.25,-1600
  Bottom Layer w8: R354.1@-1471.38,-1704 R354.1@-1471.38,-1704 C245.1@-1471.42,-1636 -1470.47,-1636 -1447.18,-1612.71 -1440.66,-1612.71 v1(-1437.02,-1609.07)
NetC246_1: C246.1 R353.1 U23.5 | length 394.5
  Top Layer w8: U23.5@1162.75,-1550 1180.5,-1550 1231.93,-1601.43 1231.93,-1631.93 v1(1275,-1675)
  Bottom Layer w8: v1(1275,-1675) 1276,-1674 1300.5,-1674 1304.5,-1670 1363.72,-1670 1397.72,-1704 R353.1@1398.62,-1704 C246.1@1471.42,-1704
NetC267_1: C267.1 R376.1 U46.1 | length 346.4
  Bottom Layer w8: U46.1@1311.93,-2717.4 1301.1,-2717.4 1288.5,-2704.8 1284.46,-2704.8 1276.31,-2696.64 1276.31,-2554.17 1340.47,-2490 C267.1@1341.42,-2490 R376.1@1341.38,-2422 R376.1@1341.38,-2422
NetC268_1: C268.1 R377.1 U47.1 | length 276.9
  Bottom Layer w8: R377.1@-1398.62,-2422 -1397.72,-2422 -1357.24,-2462.48 -1357.24,-2475.14 -1342.37,-2490 C268.1@-1341.42,-2490 -1340.47,-2490 -1295,-2535.47 -1295,-2633.8 -1303.8,-2642.6 U47.1@-1311.93,-2642.6
NetD1_2: D1.2 R171.1 R172.1 | length 208.3
  Top Layer w8: D1.2@-4100,2333.66 -4098.66,2335 v1(-4055,2335)
  Bottom Layer w8: v1(-4055,2335) -4031.38,2358.62 R172.1@-3970,2358.62 R171.1@-3902,2358.62
NetD2_2: D2.2 R170.1 | length 140
  Top Layer w8: v1(-3835,2255) -3800,2290 D2.2@-3800,2333.66
  Bottom Layer w8: v1(-3835,2255) -3835,2300.38 R170.1@-3834,2301.38
NetD3_2: D3.2 R167.1 | length 178.4
  Top Layer w8: v1(-3500,2290) D3.2@-3500,2333.66
  Bottom Layer w8: R167.1@-3630,2301.38 -3516.52,2301.38 -3505.14,2290 v1(-3500,2290)
NetD6_1: D6.1 R63.2 U7.6 | length 2906.5
  Top Layer w8: R63.2@-2357.42,273.96 R63.2@-2371.38,260 -2215,260 -2090,385 v1(-1905,385) ; v1(-1572.5,1839.09) -1404.43,1839.09 -1381.72,1816.38 -1363.25,1816.38 -1341.88,1795 -1245,1795 -1216.25,1766.25 -1216.25,1635.75 -1180.5,1600 U7.6@-1162.75,1600
  Bottom Layer w8: v1(-1905,385) -1901.36,381.36 -1893.79,381.36 -1892.43,380 -1875,380 -1535,720 -1535,1117.02 -1571.98,1154 -1664.31,1154 -1669,1158.69 -1669,1745.76 -1575.67,1839.09 v1(-1572.5,1839.09)
NetD6_2: D6.2 R187.1 | length 108.1
  Top Layer w8: D6.2@-1318.66,1836 -1289.14,1865.53 -1289.14,1871.36 v1(-1285.5,1875)
  Bottom Layer w8: R187.1@-1331.54,1885 -1321.54,1875 v1(-1285.5,1875) v1@-1289.14,1878.64
NetD7_1: D7.1 R62.2 U8.8 | length 8104.1
  Top Layer w8: R62.2@-2371.38,328 -2181.76,328 -2094.76,415 v1(-1970,415) ; v1(-1574.73,1310.27) -1579.55,1310.27 -1598,1328.72 -1598,2607.25 -1153.25,3052 1139.86,3052 1515,2676.86 1515,1931.31 1500,1916.31 1500,1855 1469.5,1824.5 1444.44,1824.5 1432.94,1836 D7.1@1401.34,1836 ; U8.8@1377.25,1350 1359.5,1350 1270,1439.5 1270,1700.66 D7.1@1403.34,1834
  Bottom Layer w8: v1(-1970,415) -1970,413.94 -1911.06,355 -1875,355 -1519,711 -1519,1123.64 -1565.36,1170 -1625.56,1170 -1641,1185.44 -1641,1209 -1650.99,1218.99 -1650.99,1271.14 -1633.24,1288.88 -1596.12,1288.88 v1(-1574.73,1310.27)
NetD7_2: D7.2 R186.1 | length 123.2
  Top Layer w8: v1(1275,1840) D7.2@1320.66,1840
  Bottom Layer w8: v1(1275,1840) 1278.64,1843.64 1294.19,1843.64 1331.54,1880.98 R186.1@1331.54,1885
NetD12_1: D12.1 R68.2 U7.8 | length 2175.5
  Top Layer w8: R68.2@-2371.38,192 -2370.47,192 -2356.52,205.96 -2356.52,206.86 -2319.38,244 -2191,244 -2075,360 -1968.97,360 -1958.74,349.77 -1904.16,349.77 -1865.18,388.76 v1(-1865.18,435.41) ; v1(-1560.5,1106.45) -1560.5,1109.5 -1525.62,1144.38 -1420.96,1144.38 D12.1@-1401.34,1164 -1401.34,1269.19 -1336.5,1334.03 -1336.5,1627 -1359.5,1650 U7.8@-1377.25,1650
  Bottom Layer w8: v1(-1865.18,435.41) -1551,749.58 -1551,1060.56 -1563.03,1072.59 -1563.03,1103.92 v1(-1560.5,1106.45)
NetD12_2: D12.2 R209.1 | length 123.7
  Top Layer w8: D12.2@-1318.66,1164 -1317.66,1165 v1(-1275,1165)
  Bottom Layer w8: R209.1@-1331.54,1115 -1331.54,1119.02 -1289.19,1161.36 -1278.64,1161.36 v1(-1275,1165)
NetD13_1: D13.1 R73.2 U8.6 | length 8903.9
  Top Layer w8: R73.2@-2371.38,56 -2370.47,56 -2356.52,69.96 -2339.39,69.96 -2335.42,73.93 v1(-2309.89,73.93) ; v1(-1710,975) -1710,2608.39 -1186.39,3132 1173,3132 1585,2720 1585,2697.37 1598,2684.37 1598,2494.44 1585,2481.44 1585,1200.19 1605.5,1179.69 v1(1605.5,1175) ; U8.6@1162.75,1400 1180.5,1400 1203.5,1377 1203.5,1246.5 v1(1240,1210) 1244.19,1210 1254.19,1200 1365.34,1200 D13.1@1401.34,1164
  Bottom Layer w8: v1(-2309.89,73.93) -2309.89,75.11 -2195,190 -2195,490 v1(-1710,975) ; v1(1240,1210) 1278.22,1171.78 1444.83,1171.78 1456.61,1160 1585.36,1160 1600.36,1175 v1(1605.5,1175)
NetD13_2: D13.2 R208.1 | length 109.9
  Top Layer w8: v1(1285,1115) 1287.73,1117.73 1287.73,1133.06 D13.2@1318.66,1164
  Bottom Layer w8: v1@1285,1114.55 v1(1285,1115) R208.1@1331.54,1115
NetD16_2: D16.2 R229.1 | length 358.2
  Top Layer w8: v1(-2490,600) D16.2@-2441.34,600
  Bottom Layer w8: R229.1@-2771.38,668 -2662.83,668 -2594.83,600 v1(-2490,600)
NetD17_2: D17.2 R59.1 | length 336.3
  Top Layer w8: R59.1@-2771.38,532 -2682,532 -2667,517 D17.2@-2441.34,517
NetD18_2: D18.2 R61.1 | length 345.8
  Top Layer w8: R61.1@-2771.38,396 -2770.47,396 -2732.47,434 D18.2@-2441.34,434
NetD21_1: D21.1 R257.2 U22.6 | length 2517.4
  Top Layer w8: v1(-1474.33,-1146.14) -1420.96,-1146.14 -1420.96,-1144.38 -1365,-1200.34 -1365,-1215.5 -1180.5,-1400 U22.6@-1162.75,-1400
  Bottom Layer w8: R257.2@-2771.38,124 -2759.2,111.83 -2745.76,111.83 -2719.44,85.5 -2673.5,39.56 -2673.5,-42.18 -2682.5,-51.18 -2682.5,-86.18 -2707.61,-111.29 -2707.61,-117.09 -2712.5,-121.98 -2712.5,-179.87 -2731,-198.37 -2731,-256.63 -2682.63,-305 -2670,-305 -2434.75,-305 -1591.07,-1148.67 -1537.61,-1148.67 -1523.94,-1135 -1503.83,-1135 -1496.33,-1142.5 -1477.97,-1142.5 v1(-1474.33,-1146.14)
NetD21_2: D21.2 R325.1 | length 109.9
  Top Layer w8: D21.2@-1318.66,-1164 -1288.64,-1133.97 -1288.64,-1118.64 v1(-1285,-1115)
  Bottom Layer w8: R325.1@-1331.54,-1115 v1(-1285,-1115) v1@-1285,-1114.55
NetD22_1: D22.1 R261.2 U23.8 | length 8983.1
  Top Layer w8: v1(-1636.5,-1240) -1636.5,-1240.69 -1650,-1254.19 -1650,-1969.49 -1572,-2047.49 -1572,-2549.88 -1588,-2565.88 -1588,-2626.24 -1145.24,-3069 1150.24,-3069 1452.12,-2767.12 1452.12,-2447.12 1507.63,-2391.61 1507.63,-2206.95 1532,-2182.58 1532,-2148.2 1531.56,-2147.76 1531.56,-2146.84 1531.57,-2085.95 1531.56,-2053.94 1481.5,-2003.87 1481.5,-1967.19 1530,-1918.69 1530,-1851.83 1499,-1820.83 1499,-1261.66 D22.1@1401.34,-1164 1335,-1230.34 1335,-1625.5 1359.5,-1650 U23.8@1377.25,-1650
  Bottom Layer w8: R261.2@-2771.38,56 -2757.42,42.04 -2750.98,42.04 -2719.44,10.5 -2689.5,-19.44 -2689.5,-35.56 -2698.5,-44.56 -2698.5,-79.56 -2723.61,-104.67 -2723.61,-110.46 -2728.5,-115.35 -2728.5,-159.66 -2747,-178.16 -2747,-263.25 -2615.75,-394.5 -2591.56,-394.5 -2466.06,-520 -2295,-520 -1636.5,-1178.5 v1(-1636.5,-1240)
NetD22_2: D22.2 R324.1 | length 136.5
  Top Layer w8: v1(1268.16,-1163.16) 1317.82,-1163.16 D22.2@1318.66,-1164
  Bottom Layer w8: v1(1268.16,-1163.16) 1291.53,-1139.78 1310.77,-1139.78 1331.54,-1119.02 R324.1@1331.54,-1115
NetD27_1: D27.1 R254.2 U22.8 | length 3124.7
  Top Layer w8: v1(-1545,-1120) -1545,-1183.44 -1544,-1184.44 -1544,-1308.44 -1495.25,-1357.19 -1495.25,-1445.81 -1426.56,-1514.5 -1419.47,-1514.5 -1410.97,-1523 -1343.53,-1523 -1340.01,-1519.49 -1336.5,-1519.49 ; D27.1@-1401.34,-1836 -1401.34,-1730.81 -1336.5,-1665.97 -1336.5,-1523 -1336.5,-1519.49 ; U22.8@-1377.25,-1350 -1359.5,-1350 -1336.5,-1373 -1336.5,-1519.49
  Bottom Layer w8: R254.2@-2771.38,192 -2770.47,192 -2655,76.53 -2655,-46.31 -2666.5,-57.81 -2666.5,-92.81 -2691.61,-117.92 -2691.61,-123.72 -2696.5,-128.61 -2696.5,-186.5 -2715,-205 -2715,-250 -2676,-289 -2428.12,-289 -1597.12,-1120 v1(-1545,-1120)
NetD27_2: D27.2 R359.1 | length 137.8
  Top Layer w8: D27.2@-1318.66,-1836 -1312.66,-1830 v1(-1270,-1830)
  Bottom Layer w8: R359.1@-1331.54,-1885 -1331.54,-1880.98 -1284.19,-1833.64 -1273.64,-1833.64 v1(-1270,-1830)
NetD28_1: D28.1 R249.2 U23.6 | length 8288
  Top Layer w8: v1(-2680,-225) -2680,-360 v1(-2620,-420) ; v1(-1562.5,-2589.51) -1565,-2592.01 -1565,-2626.61 -1138.61,-3053 1143.61,-3053 1436,-2760.61 1436,-2440.61 1490.5,-2386.11 1490.5,-2201.45 1516,-2175.95 1516,-2154.83 1515.56,-2154.39 1515.56,-2140.22 1515.57,-2092.58 ; U23.6@1162.75,-1600 1180.5,-1600 1211.88,-1631.38 1211.88,-1634.5 1219,-1641.63 1219,-1766.47 1252.91,-1800.38 1365.72,-1800.38 D28.1@1401.34,-1836 1420.96,-1855.62 1435.97,-1855.62 1484.93,-1904.59 1484.93,-1908.57 1488.04,-1911.68 1488.04,-1938.02 1465.5,-1960.56 1465.5,-2010.5 1515.56,-2060.56 1515.56,-2092.57
  Bottom Layer w8: R249.2@-2771.38,260 -2770.47,260 -2691,180.53 -2691,135.15 -2635,79.15 -2635,-48.94 -2650.5,-64.44 -2650.5,-99.44 -2675.61,-124.55 -2675.61,-130.34 -2680,-134.73 v1(-2680,-225) ; v1(-2620,-420) -2495,-545 -2295,-545 -1785,-1055 -1785,-2370.31 -1780.31,-2375 -1779.61,-2375 -1565.09,-2589.51 v1(-1562.5,-2589.51)
NetD28_2: D28.2 R358.1 | length 116.5
  Top Layer w8: v1(1280,-1885) 1283.64,-1881.36 1283.64,-1871.03 D28.2@1318.66,-1836
  Bottom Layer w8: v1(1280,-1885) R358.1@1331.54,-1885
NetD31_2: D31.2 R156.2 | length 119.9
  Bottom Layer w8: R156.2@-440.9,3585 -440.9,3688.24 D31.2@-429.13,3700
NetD32_2: D32.2 R157.2 | length 119.9
  Bottom Layer w8: D32.2@-3170.87,3700 -3159.1,3688.24 R157.2@-3159.1,3585
NetD41_2: D41.2 R384.2 | length 119.9
  Bottom Layer w8: R384.2@-440.9,-3585 -440.9,-3688.24 D41.2@-429.13,-3700
NetD42_2: D42.2 R385.2 | length 119.9
  Bottom Layer w8: D42.2@-3170.87,-3700 -3170.87,-3596.76 R385.2@-3159.1,-3585
NetJ8_3: J8.3 R118.1 | length 323.4
  Top Layer w8: R118.1@-2371.38,-1100 -2366.38,-1105 J8.3@-2050,-1105
NetJ8_4: J8.4 R115.1 | length 451.6
  Top Layer w8: R115.1@-2371.38,-1032 -2106.9,-1032 -2079.36,-1059.54 -1995.46,-1059.54 J8.4@-1950,-1105
NetJ8_5: J8.5 R120.1 | length 336.7
  Top Layer w8: R120.1@-2371.38,-1168 -2087,-1168 J8.5@-2050,-1205
NetJ8_6: J8.6 R124.1 | length 446.2
  Top Layer w8: R124.1@-2371.38,-1236 -2201.07,-1236 -2186.61,-1250.46 -1995.46,-1250.46 J8.6@-1950,-1205
NetJ8_7: J8.7 R128.1 | length 321.8
  Top Layer w8: R128.1@-2371.38,-1304 -2370.38,-1305 J8.7@-2050,-1305
NetJ8_8: J8.8 R132.1 | length 449.1
  Top Layer w8: R132.1@-2371.38,-1372 -2081.3,-1372 -2059.76,-1350.46 -1995.46,-1350.46 J8.8@-1950,-1305
NetJ8_9: J8.9 R134.1 | length 335.9
  Top Layer w8: R134.1@-2371.38,-1440 -2085,-1440 J8.9@-2050,-1405
NetJ8_10: J8.10 R136.1 | length 464
  Top Layer w8: R136.1@-2371.38,-1508 -2117.3,-1508 -2068.83,-1459.54 -2004.54,-1459.54 J8.10@-1950,-1405
NetMH2_1: MH2.1 R5.2 R6.2
NetQ1_4: Q1.4 Q2.4 R9.2 U1.10 | length 889.6
  Top Layer w8: Q2.4@-3734.88,3560 -3735,3560.12 v1(-3735,3595) -3733.54,3593.54 v1@-3733.54,3585 ; Q1.4@-3734.88,3860 -3721.89,3860 -3705.53,3876.36 -3698.64,3876.36 v1(-3695,3880) ; R9.2@-3475,3453.62 -3463.35,3465.27 -3449.73,3465.27 -3430,3485 -3430,3518.23 -3433.73,3521.96 -3433.73,3546.01 U1.10@-3435.63,3547.91 ; U1.10@-3435.32,3548.23 -3435.32,3599.68 v1(-3435,3600)
  Bottom Layer w8: v1(-3695,3880) -3735,3840 v1(-3735,3595) -3714.5,3574.5 -3460.5,3574.5 v1(-3435,3600)
NetR1_2: R1.2 R2.1 | length 68
  Top Layer w8: R1.2@-3543,3873.62 R2.1@-3475,3873.62
NetR2_2: R2.2 R3.1 U1.3 | length 187.1
  Top Layer w8: U1.3@-3475,3722.09 R2.2@-3475,3816.38 -3475,3817.28 -3433.52,3858.76 -3420.96,3858.76 -3407,3872.72 R3.1@-3407,3873.62
NetR3_2: R3.2 R4.1 U1.2 | length 182.3
  Top Layer w8: U1.2@-3455.31,3722.09 -3455.31,3767.16 -3407,3815.47 R3.2@-3407,3816.38 R4.1@-3339,3816.38
NetR4_2: R4.2 R7.1 U1.6 | length 606.2
  Top Layer w8: R7.1@-3611,3453.62 -3611,3454.53 -3575.53,3490 -3550,3490 -3533.14,3506.86 -3533.14,3507 -3514.37,3525.77 U1.6@-3514.37,3547.91 -3515.5,3549.04 -3515.5,3624.5 -3457.96,3682.04 -3401.9,3682.04 -3309.04,3774.89 -3309.04,3842.76 -3339,3872.72 R4.2@-3339,3873.62
NetR8_1: R8.1 U1.7 | length 114.3
  Top Layer w8: R8.1@-3543,3453.62 -3543,3454.53 -3494.68,3502.84 U1.7@-3494.68,3547.91
NetR9_1: R9.1 R10.2 | length 65
  Top Layer w8: R9.1@-3465,3401.38 R10.2@-3400,3401.38
NetR58_1: R58.1 R59.2 | length 92.8
  Top Layer w8: R59.2@-2828.62,532 -2827.72,532 -2786.24,573.48 -2786.24,586.04 -2772.28,600 R58.1@-2771.38,600
NetR60_1: R60.1 R61.2 | length 92.8
  Top Layer w8: R61.2@-2828.62,396 -2827.72,396 -2786.24,437.48 -2786.24,450.04 -2772.28,464 R60.1@-2771.38,464
NetR64_1: R64.1 R253.2 | length 102.1
  Top Layer w8: R64.1@-647.17,250 -645,252.17 v1(-645,300)
  Bottom Layer w8: R253.2@-647.83,250 -645,252.83 v1(-645,300)
NetR64_2: R64.2 R252.1 | length 102.1
  Top Layer w8: v1(-545,300) -545,252.17 R64.2@-542.83,250
  Bottom Layer w8: v1(-545,300) -545,252.83 R252.1@-542.17,250
NetR65_1: R65.1 R252.2 | length 102.1
  Top Layer w8: R65.1@-437.17,250 -435,252.17 v1(-435,300)
  Bottom Layer w8: R252.2@-437.83,250 -435,252.83 v1(-435,300)
NetR65_2: R65.2 R251.1 | length 102.1
  Top Layer w8: v1(-335,300) -335,252.17 R65.2@-332.83,250
  Bottom Layer w8: v1(-335,300) -335,252.83 R251.1@-332.17,250
NetR66_1: R66.1 R251.2 | length 102.1
  Top Layer w8: v1(-230,300) -230,252.83 R66.1@-227.17,250
  Bottom Layer w8: v1(-230,300) -230,252.17 R251.2@-227.83,250
NetR67_1: R67.1 U14.10 | length 177.6
  Top Layer w8: R67.1@-1331.38,204 -1330.47,204 -1251.47,125 U14.10@-1186.5,125
NetR69_1: R69.1 U15.14 | length 170.1
  Top Layer w8: U15.14@1186.5,75 1250,75 1297.04,122.04 1317.42,122.04 R69.1@1331.38,136
NetR70_1: R70.1 U14.11 | length 147.8
  Top Layer w8: R70.1@-1331.38,68 -1324.38,75 U14.11@-1186.5,75
NetR72_1: R72.1 R267.2 R274.1 | length 512.7
  Top Layer w8: v1(570,80) 599.38,80 R72.1@611.38,68
  Bottom Layer w8: v1(570,80) 549.5,59.5 549.5,0.5 588.04,-38.04 637.76,-38.04 667.72,-68 R267.2@668.62,-68 670.42,-69.8 694.8,-69.8 752.17,-127.17 R274.1@752.17,-250
NetR76_1: R76.1 R253.1 R260.2 | length 511.3
  Top Layer w8: R76.1@-611.38,-68 -609.38,-70 v1(-570,-70)
  Bottom Layer w8: R253.1@-752.17,250 -760,242.17 -760,125 -716.96,81.96 -682.58,81.96 R260.2@-668.62,68 -667.72,68 -634.24,34.52 -590.39,34.52 -586.73,30.86 -586.64,30.86 -545,-10.78 -545,-45 v1(-570,-70)
NetR78_1: R78.1 U15.11 | length 147.8
  Top Layer w8: U15.11@1186.5,-75 1324.38,-75 R78.1@1331.38,-68
NetR80_1: R80.1 U14.14 | length 170.1
  Top Layer w8: R80.1@-1331.38,-136 -1317.42,-122.04 -1297.04,-122.04 -1250,-75 U14.14@-1186.5,-75
NetR82_1: R82.1 U15.10 | length 177.6
  Top Layer w8: U15.10@1186.5,-125 1251.47,-125 1330.47,-204 R82.1@1331.38,-204
NetR84_1: R84.1 R276.2 | length 102.1
  Top Layer w8: R84.1@227.17,-250 230,-252.83 v1(230,-300)
  Bottom Layer w8: R276.2@227.83,-250 230,-252.17 v1(230,-300)
NetR85_1: R85.1 R275.2 | length 102.1
  Top Layer w8: R85.1@437.17,-250 440,-252.83 v1(440,-300)
  Bottom Layer w8: R275.2@437.83,-250 440,-252.17 v1(440,-300)
NetR85_2: R85.2 R276.1 | length 102.1
  Top Layer w8: R85.2@332.83,-250 335,-252.17 v1(335,-300)
  Bottom Layer w8: R276.1@332.17,-250 335,-252.83 v1(335,-300)
NetR86_1: R86.1 R274.2 | length 102.1
  Top Layer w8: R86.1@647.17,-250 650,-252.83 v1(650,-300)
  Bottom Layer w8: R274.2@647.83,-250 650,-252.17 v1(650,-300)
NetR86_2: R86.2 R275.1 | length 102.1
  Top Layer w8: R86.2@542.83,-250 545,-252.17 v1(545,-300)
  Bottom Layer w8: R275.1@542.17,-250 545,-252.83 v1(545,-300)
NetR89_2: R89.2 U35.13 | length 1177.2
  Top Layer w8: R89.2@-2771.38,-420 -2757.42,-433.96 -2642.11,-433.96 -2626.11,-449.96 -2281.52,-449.96 -2205.78,-374.22 -2205.78,34.22 v1(-2205,35)
  Bottom Layer w8: v1(-2205,35) -2205,78.56 -2145.38,138.18 -2119.25,138.18 U35.13@-2116.25,141.18
NetR91_2: R91.2 U35.12 | length 1193
  Top Layer w8: R91.2@-2771.38,-488 -2741.42,-517.96 -2326.89,-517.96 -2170,-361.06 v1(-2170,75)
  Bottom Layer w8: v1(-2170,75) -2166.36,78.64 -2166.36,91.61 -2145.38,112.59 -2119.25,112.59 U35.12@-2116.25,115.59
NetR93_1: R93.1 R284.1 R288.1 | length 172.1
  Top Layer w8: v1(-2870,-590) -2866.36,-586.36 -2859.89,-586.36 -2829.53,-556 R93.1@-2826.62,-556 R93.1@-2828.62,-558
  Bottom Layer w8: v1@-2859.89,-586.36 -2829.53,-556 R288.1@-2828.62,-556 R284.1@-2828.62,-488
NetR95_1: R95.1 R298.2 U20.3 | length 508.5
  Top Layer w8: v1(-2684.19,-714.86) -2684.05,-715 -2617.84,-715 -2590.43,-742.41 -2590.43,-746.27 -2587.29,-749.41 -2544.45,-749.41 U20.3@-2541.06,-746.01 ; U20.3@-2541.01,-746.01 -2442.7,-647.7 -2442.7,-637.96 -2428.75,-624 R95.1@-2428.62,-624
  Bottom Layer w8: R298.2@-2828.62,-692 -2827.72,-692 -2797.76,-662.04 -2737.96,-662.04 -2685.14,-714.86 v1(-2684.19,-714.86)
NetR97_2: R97.2 U17.4 | length 263.5
  Top Layer w8: R97.2@-2771.38,-692 -2768.74,-689.36 -2673.63,-689.36 -2667.49,-695.5 -2580.5,-695.5 -2551.77,-666.77 U17.4@-2551.77,-638.4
